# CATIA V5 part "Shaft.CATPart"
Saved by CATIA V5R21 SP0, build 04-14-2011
Part number: Part4
Bounding box of the stored display mesh (mm): x -10 to 60, y -9 to 9, z 0 to 55
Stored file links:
  D:\CATIA V5R21 E-RESOURCES\CATIA-V5R21\catia-v5r21-prt\c16-catia-v5r20-prt\Gear Joint-(16-53)\CAT_V5R21_Shaft.CATPart
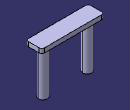
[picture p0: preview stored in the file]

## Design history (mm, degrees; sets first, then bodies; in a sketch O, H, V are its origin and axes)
Body1 (main body)
  Sketch1 on xy-plane, origin (0, 0, 0), H (1, 0, 0), V (0, 1, 0)
    circle A1 centre (0, 0) radius 5
    point P1 (30.2964, -4.0836)
    circle A2 centre (50, 0) radius 5
    point P2 (50, 0)
    radius A1 = 5
    radius A2 = 5
    distance P2 O = 50
    coincidence: P2 H
  Pad1: profile Sketch1, direction (0, 0, 1), length 50
  Sketch2 on end face of Pad1, origin (0, 0, 50), H (1, 0, 0), V (0, 1, 0)
    line L1 (-10, 9) -> (60, 9)
    line L2 (60, 9) -> (60, -9)
    line L3 (60, -9) -> (-10, -9)
    line L4 (-10, -9) -> (-10, 9)
    length L2 = 18
    distance L3 H = 9
    length L1 = 70
    distance L4 V = 10
    horizontal: L1 H, L3 H
    vertical: L2 V, L4 V
  Pad2: profile Sketch2, direction (0, 0, 1), length 5
  Fillet1: radius 3, on edge [face of Pad1 from Sketch1.A1 | start face of Pad2]; edge [face of Pad1 from Sketch1.A2 | start face of Pad2]
  Fillet2: radius 3, on edge [face of Pad2 from Sketch2.L4 | face of Pad2 from Sketch2.L1]; edge [face of Pad2 from Sketch2.L3 | face of Pad2 from Sketch2.L4]; edge [face of Pad2 from Sketch2.L1 | face of Pad2 from Sketch2.L2]; edge [face of Pad2 from Sketch2.L2 | face of Pad2 from Sketch2.L3]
